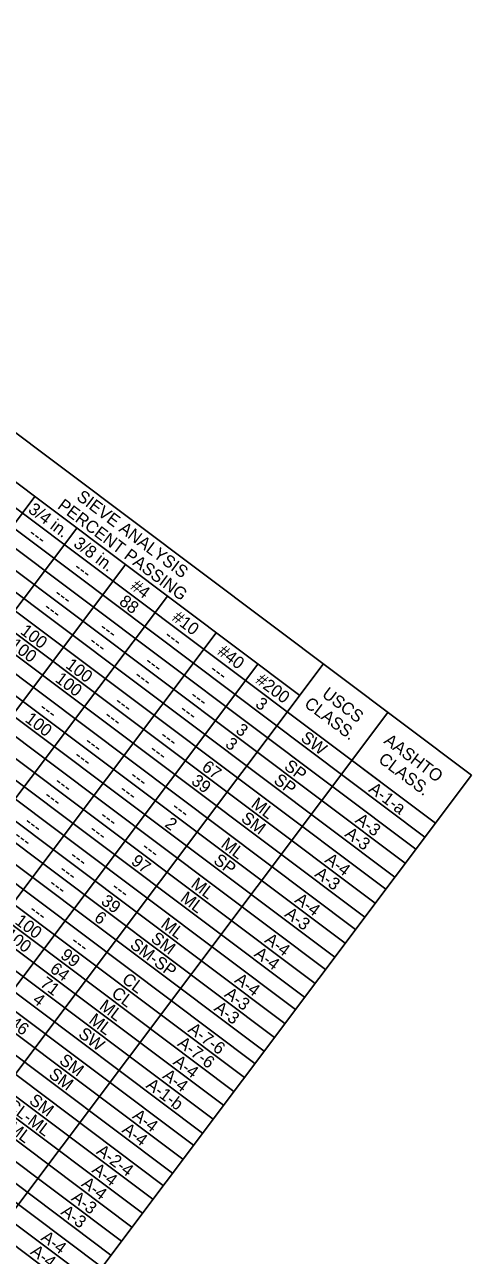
# Model space of a CAD drawing. Extents: x 627484.2 to 627514.4, y 367972.1 to 367996.9.
# Drawn here: x 627512.36 to 627514.36, y 367980.14 to 367985.65 of the extents above; entities that cross this region are included whole.
import ezdxf

# ---------------------------------------------------------------- set-up
doc = ezdxf.new("R2010")
doc.units = 0
doc.layers.add('Default', color=7, linetype='Continuous')

msp = doc.modelspace()

# ---------------------------------------------------------------- linework, layer by layer
at = {"layer": 'Default'}
for p, q in [((627509.8821, 367985.648), (627514.3574, 367982.2875)), ((627509.7211, 367985.4336), (627514.1964, 367982.0731)), ((627509.6743, 367985.3712), (627514.1495, 367982.0107)), ((627509.6333, 367985.3166), (627514.1086, 367981.9561)), ((627509.5865, 367985.2543), (627514.0617, 367981.8938)), ((627509.5396, 367985.1919), (627514.0149, 367981.8314)), ((627509.4987, 367985.1373), (627513.9739, 367981.7768)), ((627509.4518, 367985.075), (627513.9271, 367981.7145)), ((627509.405, 367985.0126), (627513.8802, 367981.6521)), ((627509.364, 367984.958), (627513.8393, 367981.5975)), ((627509.3172, 367984.8956), (627513.7924, 367981.5351)), ((627509.2703, 367984.8333), (627513.7456, 367981.4728)), ((627509.2294, 367984.7787), (627513.7046, 367981.4182)), ((627509.1825, 367984.7163), (627513.6578, 367981.3558)), ((627509.1357, 367984.6539), (627513.6109, 367981.2934)), ((627509.0947, 367984.5994), (627513.57, 367981.2389)), ((627509.0479, 367984.537), (627513.5231, 367981.1765)), ((627509.001, 367984.4746), (627513.4763, 367981.1141)), ((627508.9542, 367984.4122), (627513.4294, 367981.0517)), ((627508.9132, 367984.3577), (627513.3885, 367980.9972)), ((627508.8664, 367984.2953), (627513.3416, 367980.9348)), ((627508.8195, 367984.2329), (627513.2948, 367980.8724)), ((627508.7727, 367984.1705), (627513.248, 367980.81)), ((627508.7259, 367984.1082), (627513.2011, 367980.7477)), ((627508.679, 367984.0458), (627513.1543, 367980.6853)), ((627508.638, 367983.9912), (627513.1133, 367980.6307)), ((627508.5912, 367983.9289), (627513.0665, 367980.5684)), ((627508.5444, 367983.8665), (627513.0196, 367980.506)), ((627508.5034, 367983.8119), (627512.9786, 367980.4514)), ((627511.9988, 367983.8391), (627513.5893, 367982.6448)), ((627508.4566, 367983.7495), (627512.9318, 367980.389)), ((627508.4097, 367983.6872), (627512.885, 367980.3267)), ((627508.3629, 367983.6248), (627512.8381, 367980.2643)), ((627508.3161, 367983.5624), (627512.7913, 367980.2019)), ((627510.7152, 367981.2854), (627512.4042, 367983.5347)), ((627508.2692, 367983.5), (627512.7445, 367980.1395)), ((627508.2282, 367983.4455), (627512.7035, 367980.085)), ((627508.1814, 367983.3831), (627512.6566, 367980.0226)), ((627510.9023, 367981.1449), (627512.5913, 367983.3942)), ((627508.1346, 367983.3207), (627512.6098, 367979.9602)), ((627511.1206, 367980.9809), (627512.8096, 367983.2303)), ((627511.3077, 367980.8404), (627512.9968, 367983.0897)), ((627511.526, 367980.6765), (627513.2151, 367982.9258)), ((627511.7131, 367980.536), (627513.4022, 367982.7853)), ((627511.9003, 367980.3955), (627513.6947, 367982.7851)), ((627512.1887, 367980.1789), (627513.9831, 367982.5685)), ((627513.5337, 367982.5707), (627514.1964, 367982.0731)), ((627512.563, 367979.8978), (627514.3574, 367982.2875))]:
    msp.add_line(p, q, dxfattribs=at)

# ---------------------------------------------------------------- texts
for s, p in [('PERCENT PASSING', (627512.5013, 367983.4855)), ('SIEVE ANALYSIS', (627512.5861, 367983.5251)), ('3/4 in.', (627512.3699, 367983.4682)), ('---', (627512.371, 367983.3606)), ('3/8 in.', (627512.5726, 367983.3159)), ('---', (627512.5738, 367983.2084)), ('#4', (627512.8276, 367983.1244)), ('---', (627512.4859, 367983.0914)), ('88', (627512.777, 367983.0558)), ('---', (627512.4391, 367983.0291)), ('#10', (627513.014, 367982.9845)), ('100', (627512.3349, 367982.9244)), ('---', (627512.6886, 367982.9392)), ('---', (627512.9792, 367982.9039)), ('100', (627512.288, 367982.8621)), ('---', (627512.6418, 367982.8768)), ('#40', (627513.2167, 367982.8323)), ('100', (627512.5376, 367982.7722)), ('---', (627512.8914, 367982.787)), ('---', (627513.1819, 367982.7517)), ('100', (627512.4908, 367982.7098)), ('---', (627512.8445, 367982.7246)), ('#200', (627513.3875, 367982.704)), ('---', (627513.0941, 367982.6348)), ('USCS', (627513.6848, 367982.6421)), ('---', (627512.4193, 367982.5806)), ('---', (627512.7567, 367982.6077)), ('---', (627513.0472, 367982.5724)), ('3', (627513.3866, 367982.598)), ('CLASS.', (627513.6056, 367982.5984)), ('100', (627512.3561, 367982.5305)), ('---', (627512.7099, 367982.5453)), ('3', (627513.2988, 367982.481)), ('SW', (627513.5895, 367982.4456)), ('---', (627512.6221, 367982.4284)), ('---', (627512.9594, 367982.4555)), ('3', (627513.252, 367982.4187)), ('AASHTO', (627513.9618, 367982.4341)), ('---', (627512.5752, 367982.366)), ('---', (627512.9126, 367982.3931)), ('CLASS.', (627513.9369, 367982.3496)), ('67', (627513.1467, 367982.3148)), ('SP', (627513.5152, 367982.3186)), ('---', (627512.4874, 367982.249)), ('---', (627512.8248, 367982.2761)), ('39', (627513.0998, 367982.2525)), ('SP', (627513.4684, 367982.2562)), ('---', (627512.4406, 367982.1867)), ('---', (627512.7779, 367982.2138)), ('A-1-a', (627513.8937, 367982.2173)), ('---', (627513.0119, 367982.1356)), ('ML', (627513.3675, 367982.149)), ('---', (627512.6901, 367982.0968)), ('2', (627512.9813, 367982.061)), ('SM', (627513.3224, 367982.0853)), ('A-3', (627513.8337, 367982.0794)), ('---', (627512.3527, 367982.0697)), ('---', (627512.6433, 367982.0344)), ('A-3', (627513.7869, 367982.017)), ('---', (627512.3059, 367982.0073)), ('ML', (627513.2328, 367981.9697)), ('---', (627512.5555, 367981.9175)), ('97', (627512.8305, 367981.8938)), ('---', (627512.8772, 367981.9563)), ('SP', (627513.199, 367981.8975)), ('A-4', (627513.6975, 367981.9012)), ('---', (627512.5086, 367981.8551)), ('ML', (627513.0982, 367981.7904)), ('A-3', (627513.6522, 367981.8377)), ('---', (627512.4618, 367981.7927)), ('---', (627512.7426, 367981.777)), ('ML', (627513.0513, 367981.728)), ('39', (627512.6958, 367981.7146)), ('A-4', (627513.5628, 367981.7219)), ('100', (627512.3107, 367981.6257)), ('---', (627512.374, 367981.6758)), ('6', (627512.6651, 367981.6401)), ('ML', (627512.9635, 367981.6111)), ('A-3', (627513.5176, 367981.6584)), ('100', (627512.2639, 367981.5634)), ('---', (627512.5611, 367981.5353)), ('SM-SP', (627512.8252, 367981.5199)), ('SM', (627512.9185, 367981.5474)), ('A-4', (627513.4282, 367981.5426)), ('99', (627512.5143, 367981.4729)), ('A-4', (627513.3813, 367981.4802)), ('64', (627512.4672, 367981.4107)), ('71', (627512.4232, 367981.3462)), ('CL', (627512.7893, 367981.364)), ('A-4', (627513.2935, 367981.3633)), ('CL', (627512.7424, 367981.3016)), ('A-3', (627513.2483, 367981.2997)), ('4', (627512.3898, 367981.2737)), ('ML', (627512.6884, 367981.2446)), ('A-3', (627513.2014, 367981.2373)), ('ML', (627512.6415, 367981.1823)), ('46', (627512.2858, 367981.1689)), ('SW', (627512.5943, 367981.1202)), ('A-7-6', (627513.0851, 367981.1418)), ('A-7-6', (627513.0382, 367981.0794)), ('SM', (627512.5086, 367981.0016)), ('A-4', (627513.0183, 367980.9968)), ('SM', (627512.4618, 367980.9392)), ('A-4', (627512.9715, 367980.9345)), ('A-1-b', (627512.8976, 367980.8924)), ('CL-ML', (627512.2731, 367980.8005)), ('SM', (627512.374, 367980.8223)), ('A-4', (627512.8369, 367980.7551)), ('ML', (627512.2785, 367980.6989)), ('A-4', (627512.79, 367980.6928)), ('A-2-4', (627512.6751, 367980.5961)), ('A-4', (627512.6554, 367980.5134)), ('A-4', (627512.6085, 367980.4511)), ('A-3', (627512.5633, 367980.3875)), ('A-3', (627512.5164, 367980.3251)), ('A-4', (627512.427, 367980.2094)), ('A-4', (627512.3802, 367980.147))]:
    msp.add_text(s, height=0.055, rotation=323.0968, dxfattribs=at).set_placement(p)

doc.saveas('drawing.dxf')
